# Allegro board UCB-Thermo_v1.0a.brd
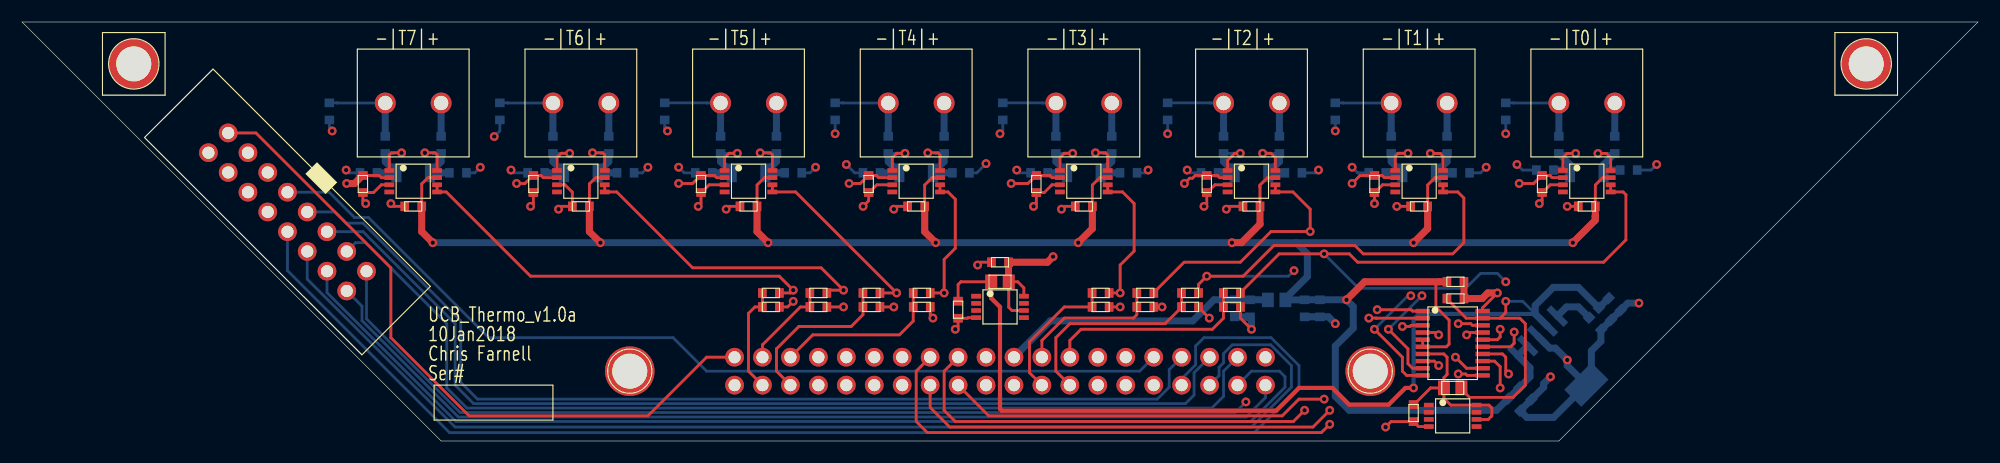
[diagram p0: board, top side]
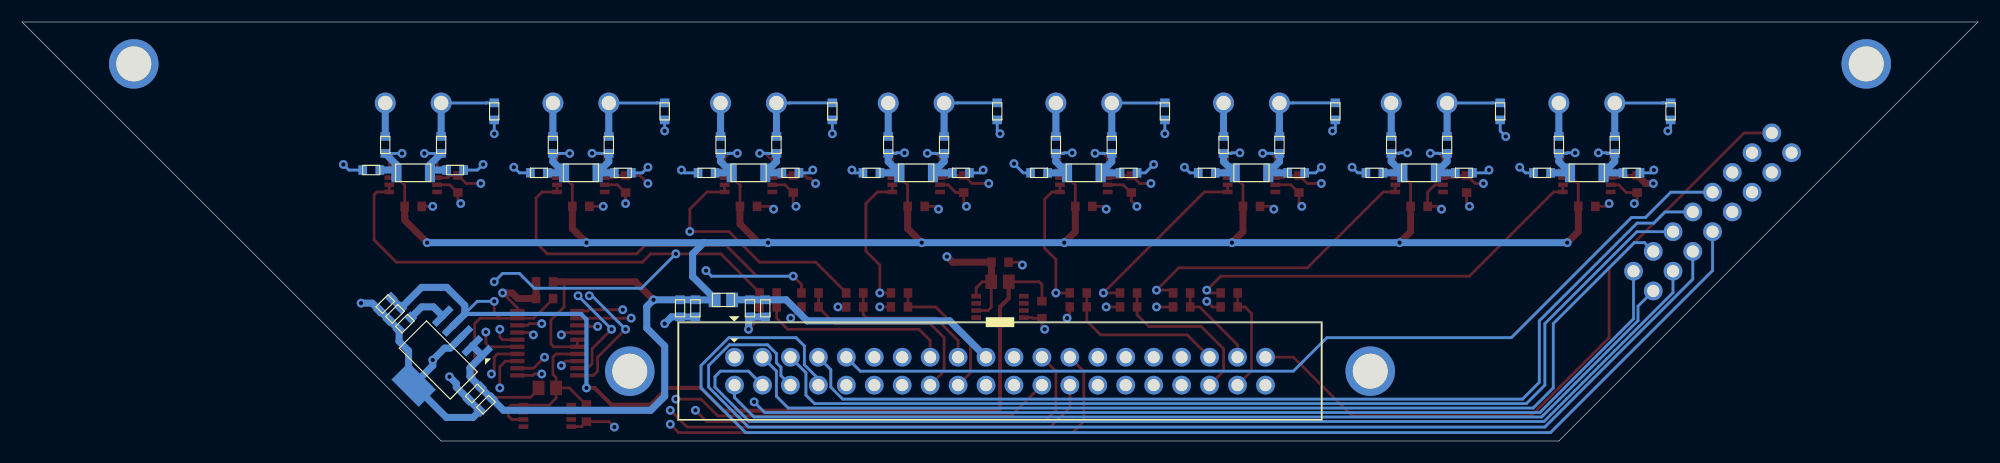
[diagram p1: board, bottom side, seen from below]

Outline 177.8 x 38.1 mm; copper layers: TOP, LAYER_2, LAYER_3, BOTTOM. Coordinates in mm from the lower left corner of the outline.
Outline path: 0,38.1 38.1,0 139.7,0 177.8,38.1 0,38.1

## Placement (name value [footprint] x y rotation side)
ADC1  AD7928BRUZ  [20-TSSOP]  130.05 8.89 0 top
C25  1uF  [C_0603]  110.24 12.06 270 bottom
C26  0.1uF  [C_0603]  111.63 12.06 270 bottom
C27  1uF  [C_0603]  116.59 12.06 270 bottom
C28  1uF  [C_0603]  85.09 11.94 270 top
C29  0.1uF  [C_0603]  117.98 12.06 270 bottom
C30  1uF  [C_0603]  88.9 16.26 0 top
C31  1uF  [C_0603]  135.64 3.3 315 bottom
C32  0.1uF  [C_0603]  136.65 4.32 315 bottom
C33  10nF  [C_0603]  143 10.67 315 bottom
C34  0.1uF  [C_0603]  143.89 11.56 315 bottom
C35  1uF  [C_0603]  144.78 12.45 315 bottom
C38  1uF  [C_0603]  130.3 14.48 0 top
C39  1uF  [C_0603]  130.3 12.95 0 top
C40  1uF  [C_0603]  126.49 2.54 90 top
C59  10uF  [C_1206]  142.24 24.38 180 bottom
C60  1uF  [C_0603]  146.05 24.64 180 bottom
C61  1uF  [C_0603]  138.43 24.64 180 bottom
C62  0.1uF  [C_0603]  142.24 21.34 180 top
C63  0.1uF  [C_0603]  138.18 23.37 90 top
C64  10uF  [C_1206]  127 24.38 180 bottom
C65  1uF  [C_0603]  130.81 24.38 180 bottom
C66  1uF  [C_0603]  123.19 24.38 180 bottom
C67  0.1uF  [C_0603]  127 21.34 180 top
C68  0.1uF  [C_0603]  122.94 23.37 90 top
C69  10uF  [C_1206]  111.76 24.38 180 bottom
C70  1uF  [C_0603]  115.57 24.38 180 bottom
C71  1uF  [C_0603]  107.95 24.38 180 bottom
C72  0.1uF  [C_0603]  111.76 21.34 180 top
C73  0.1uF  [C_0603]  107.7 23.37 90 top
C74  10uF  [C_1206]  96.52 24.38 180 bottom
C75  1uF  [C_0603]  100.58 24.38 180 bottom
C76  1uF  [C_0603]  92.46 24.38 180 bottom
C77  0.1uF  [C_0603]  96.52 21.34 180 top
C78  0.1uF  [C_0603]  92.2 23.37 90 top
C79  10uF  [C_1206]  81.28 24.38 180 bottom
C80  1uF  [C_0603]  85.34 24.38 180 bottom
C81  1uF  [C_0603]  77.22 24.38 180 bottom
C82  0.1uF  [C_0603]  81.28 21.34 180 top
C83  0.1uF  [C_0603]  76.96 23.37 90 top
C84  10uF  [C_1206]  66.04 24.38 180 bottom
C85  1uF  [C_0603]  70.1 24.38 180 bottom
C86  1uF  [C_0603]  61.98 24.38 180 bottom
C87  0.1uF  [C_0603]  66.04 21.34 180 top
C88  0.1uF  [C_0603]  61.72 23.37 90 top
C89  10uF  [C_1206]  50.8 24.38 180 bottom
C90  1uF  [C_0603]  54.86 24.38 180 bottom
C91  1uF  [C_0603]  46.74 24.38 180 bottom
C92  0.1uF  [C_0603]  50.8 21.34 180 top
C93  0.1uF  [C_0603]  46.48 23.37 90 top
C94  10uF  [C_1206]  35.56 24.38 180 bottom
C95  1uF  [C_0603]  39.62 24.38 180 bottom
C96  1uF  [C_0603]  31.5 24.38 180 bottom
C97  0.1uF  [C_0603]  35.56 21.34 180 top
C98  0.1uF  [C_0603]  30.99 23.37 90 top
J3  SFH11-PBPC-D20-ST-BK  [40-IDC-F_MNT]  88.9 6.35 270 bottom
J4  AWHW 16G-0202-T  [16-IDC-M]  24.13 20.83 225 top
J5  -  [1715721]  142.24 30.73 270 top
J6  -  [1715721]  127 30.73 270 top
J7  -  [1715721]  111.76 30.73 270 top
J8  -  [1715721]  96.52 30.73 270 top
J9  -  [1715721]  81.28 30.73 270 top
J10  -  [1715721]  66.04 30.73 270 top
J11  -  [1715721]  50.8 30.73 270 top
J12  -  [1715721]  35.56 30.73 270 top
L1  220  [L_0805]  114.05 12.83 0 bottom
MECH1  Mech_Hole  [4-40_SCREW]  10.16 34.29 0 top
MECH2  Mech_Hole  [4-40_SCREW]  167.64 34.29 0 top
R3  1k  [R_0805]  88.9 14.48 0 top
R8  1k  [R_0805]  130.05 4.83 180 top
R15  10k  [R_0603]  109.98 13.46 180 top
R16  15k  [R_0603]  109.98 12.19 0 top
R17  10k  [R_0603]  106.17 13.46 180 top
R18  15k  [R_0603]  106.17 12.19 0 top
R23  10k  [R_0603]  102.11 13.46 180 top
R24  15k  [R_0603]  102.11 12.19 0 top
R29  10k  [R_0603]  98.04 13.46 180 top
R30  15k  [R_0603]  98.04 12.19 0 top
R35  10k  [R_0603]  81.79 13.46 180 top
R36  15k  [R_0603]  81.79 12.19 0 top
R41  10k  [R_0603]  77.22 13.46 180 top
R42  15k  [R_0603]  77.22 12.19 0 top
R47  10k  [R_0603]  72.39 13.46 180 top
R48  15k  [R_0603]  72.39 12.19 0 top
R53  10k  [R_0603]  68.07 13.46 180 top
R54  15k  [R_0603]  68.07 12.19 0 top
R59  10k  [R_0603]  144.78 26.92 90 bottom
R60  10k  [R_0603]  139.7 26.92 90 bottom
R61  1Meg  [R_0603]  134.87 29.97 90 bottom
R62  1Meg  [R_0603]  119.38 29.97 90 bottom
R63  10k  [R_0603]  129.54 26.92 90 bottom
R64  10k  [R_0603]  124.46 26.92 90 bottom
R65  1Meg  [R_0603]  104.14 29.97 90 bottom
R66  10k  [R_0603]  114.3 26.92 90 bottom
R67  10k  [R_0603]  109.22 26.92 90 bottom
R68  1Meg  [R_0603]  89.15 29.97 90 bottom
R69  10k  [R_0603]  99.06 26.92 90 bottom
R70  10k  [R_0603]  93.98 26.92 90 bottom
R71  1Meg  [R_0603]  73.91 29.97 90 bottom
R72  10k  [R_0603]  83.82 26.92 90 bottom
R73  10k  [R_0603]  78.74 26.92 90 bottom
R74  1Meg  [R_0603]  58.42 29.97 90 bottom
R75  10k  [R_0603]  68.58 26.92 90 bottom
R76  10k  [R_0603]  63.5 26.92 90 bottom
R77  1Meg  [R_0603]  43.43 29.97 90 bottom
R78  10k  [R_0603]  53.34 26.92 90 bottom
R79  10k  [R_0603]  48.26 26.92 90 bottom
R80  1Meg  [R_0603]  27.94 29.97 90 bottom
R81  10k  [R_0603]  38.1 26.92 90 bottom
R82  10k  [R_0603]  33.02 26.92 90 bottom
U1  LT1009CZ  [8-MSOP]  88.9 12.19 0 top
U2  TPS79533  [SOT-223-6]  139.95 7.37 135 bottom
U4  LT1009CZ  [8-MSOP]  130.05 2.29 0 top
U7  AD8495ARMZ  [8-MSOP]  142.24 23.62 0 top
U8  AD8495ARMZ  [8-MSOP]  127 23.62 0 top
U9  AD8495ARMZ  [8-MSOP]  111.76 23.62 0 top
U10  AD8495ARMZ  [8-MSOP]  96.52 23.62 0 top
U11  AD8495ARMZ  [8-MSOP]  81.28 23.62 0 top
U12  AD8495ARMZ  [8-MSOP]  66.04 23.62 0 top
U13  AD8495ARMZ  [8-MSOP]  50.8 23.62 0 top
U14  AD8495ARMZ  [8-MSOP]  35.56 23.62 0 top

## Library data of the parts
ADC1 = AD7928BRUZ
C25-C35 C38-C40 C59-C98 = CAP NP
J3 = Header_2x20
J4 = Header_2x8
J5-J12 = Connector-2
L1 = Ind
MECH1 MECH2 = Mech_Hole
R3 R8 R15-R18 R23 R24 R29 R30 R35 R36 R41 R42 R47 R48 R53 R54 R59-R82 = R-Standard
U1 U4 = LT1009CZ
U2 = TPS795
U7-U14 = AD849X

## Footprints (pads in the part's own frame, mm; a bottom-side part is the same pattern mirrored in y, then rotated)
4-40_SCREW
  round 4.5 hole 3.175: 1(0,0)
8-MSOP
  rect 0.889x0.42 smd: 1(-2.17,0.975) 2(-2.17,0.325) 3(-2.17,-0.325) 4(-2.17,-0.975) 5(2.17,-0.975) 6(2.17,-0.325) 7(2.17,0.325) 8(2.17,0.975)
16-IDC-M
  round 1.7 hole 1.1: 1(-1.27,8.89) 2(1.27,8.89) 3(-1.27,6.35) 4(1.27,6.35) 5(-1.27,3.81) 6(1.27,3.81) 7(-1.27,1.27) 8(1.27,1.27) 9(-1.27,-1.27) 10(1.27,-1.27) 11(-1.27,-3.81) 12(1.27,-3.81) 13(-1.27,-6.35) 14(1.27,-6.35) 15(-1.27,-8.89) 16(1.27,-8.89)
20-TSSOP
  rect 1.3x0.4 smd: 1(-2.725,2.925) 2(-2.725,2.275) 3(-2.725,1.625) 4(-2.725,0.975) 5(-2.725,0.325) 6(-2.725,-0.325) 7(-2.725,-0.975) 8(-2.725,-1.625) 9(-2.725,-2.275) 10(-2.725,-2.925) 11(2.725,-2.925) 12(2.725,-2.275) 13(2.725,-1.625) 14(2.725,-0.975) 15(2.725,-0.325) 16(2.725,0.325) 17(2.725,0.975) 18(2.725,1.625) 19(2.725,2.275) 20(2.725,2.925)
40-IDC-F_MNT
  round 4.5 hole 3.175: (0,-33.655) (0,33.655)
  round 1.7 hole 1.1: 1(-1.27,-24.13) 2(1.27,-24.13) 3(-1.27,-21.59) 4(1.27,-21.59) 5(-1.27,-19.05) 6(1.27,-19.05) 7(-1.27,-16.51) 8(1.27,-16.51) 9(-1.27,-13.97) 10(1.27,-13.97) 11(-1.27,-11.43) 12(1.27,-11.43) 13(-1.27,-8.89) 14(1.27,-8.89) 15(-1.27,-6.35) 16(1.27,-6.35) 17(-1.27,-3.81) 18(1.27,-3.81) 19(-1.27,-1.27) 20(1.27,-1.27) 21(-1.27,1.27) 22(1.27,1.27) 23(-1.27,3.81) 24(1.27,3.81) 25(-1.27,6.35) 26(1.27,6.35) 27(-1.27,8.89) 28(1.27,8.89) 29(-1.27,11.43) 30(1.27,11.43) 31(-1.27,13.97) 32(1.27,13.97) 33(-1.27,16.51) 34(1.27,16.51) 35(-1.27,19.05) 36(1.27,19.05) 37(-1.27,21.59) 38(1.27,21.59) 39(-1.27,24.13) 40(1.27,24.13)
1715721
  round 1.9 hole 1.3: 1(0,2.54) 2(0,-2.54)
C_0603
  rect 0.787x0.864 smd: 1(-0.775,0) 2(0.775,0)
C_1206
  rect 0.914x1.702 smd: 1(-1.524,0) 2(1.524,0)
L_0805
  rect 1.08x1.321 smd: 1(-0.794,0) 2(0.794,0)
R_0603
  rect 0.787x0.864 smd: 1(-0.775,0) 2(0.775,0)
R_0805
  rect 1.08x1.321 smd: 1(-0.794,0) 2(0.794,0)
SOT-223-6
  rect 2.2x0.6 smd: 1(3.1,-2.54) 2(3.1,-1.27) 3(3.1,0) 4(3.1,1.27) 5(3.1,2.54)
  rect 2.2x3.5 smd: 6(-3.175,0)

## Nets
2V5_REF: C30.2 C63.2 C68.2 C73.2 C78.2 C83.2 C88.2 C93.2 C98.2 R3.2 U1.6(V+.) U1.8(V+) U7.2(REF) U8.2(REF) U9.2(REF) U10.2(REF) U11.2(REF) U12.2(REF) U13.2(REF) U14.2(REF)
3V3: ADC1.19(VDRIVE) C28.1 C34.1 C35.1 C39.1 R3.1 R8.1 U2.4(VOUT)
5V0: ADC1.5(AVDD) ADC1.6(AVDD.) C27.1 C29.1 C31.1 C32.1 C38.1 C62.1 C67.1 C72.1 C77.1 C82.1 C87.1 C92.1 C97.1 L1.2 U2.1(EN) U2.2(VIN) U7.7(+VS) U8.7(+VS) U9.7(+VS) U10.7(+VS) U11.7(+VS) U12.7(+VS) U13.7(+VS) U14.7(+VS)
5V_IDC: C25.1 C26.1 J3.19 J3.39 J4.15 L1.1
GND: ADC1.4(AGND) ADC1.8(AGND.) ADC1.17(AGND..) ADC1.20(AGND...) C25.2 C26.2 C27.2 C28.2 C29.2 C30.1 C31.2 C32.2 C33.2 C34.2 C35.2 C38.2 C39.2 C40.1 C60.1 C61.2 C62.2 C63.1 C65.1 C66.2 C67.2 C68.1 C70.1 C71.2 C72.2 C73.1 C75.1 C76.2 C77.2 C78.1 C80.1 C81.2 C82.2 C83.1 C85.1 C86.2 C87.2 C88.1 C90.1 C91.2 C92.2 C93.1 C95.1 C96.2 C97.2 C98.1 J3.20 J3.40 J4.16 R16.2 R18.2 R24.2 R30.2 R36.2 R42.2 R48.2 R54.2 R61.1 R62.1 R65.1 R68.1 R71.1 R74.1 R77.1 R80.1 U1.4(GND) U2.3(GND) U2.6(GND.) U4.4(GND) U7.3(-VS) U8.3(-VS) U9.3(-VS) U10.3(-VS) U11.3(-VS) U12.3(-VS) U13.3(-VS) U14.3(-VS)
IDC_ADC-0: J3.15 R15.2 R16.1
IDC_ADC-1: J3.16 R17.2 R18.1
IDC_ADC-2: J3.17 R23.2 R24.1
IDC_ADC-3: J3.18 R29.2 R30.1
IDC_ADC-4: J3.35 R35.2 R36.1
IDC_ADC-5: J3.36 R41.2 R42.1
IDC_ADC-6: J3.37 R47.2 R48.1
IDC_ADC-7: J3.38 R53.2 R54.1
IDC_IO-1: J3.1 J4.1
IDC_IO-2: J3.2 J4.2
IDC_IO-3: J3.3 J4.3
IDC_IO-4: J3.4 J4.4
IDC_IO-5: J3.5 J4.5
IDC_IO-6: J3.6 J4.6
IDC_IO-7: J3.7 J4.7
IDC_IO-8: J3.8 J4.8
IDC_IO-9: J3.9 J4.9
IDC_IO-10: J3.10 J4.10
IDC_IO-11: J3.11 J4.11
IDC_IO-12: J3.12 J4.12
IDC_IO-13: J3.13 J4.13
IDC_IO-14: J3.14 J4.14
SPI-ADC_5V-CH0: ADC1.16(VIN0) R15.1 U7.5(SENSE) U7.6(OUT)
SPI-ADC_5V-CH1: ADC1.15(VIN1) R17.1 U8.5(SENSE) U8.6(OUT)
SPI-ADC_5V-CH2: ADC1.14(VIN2) R23.1 U9.5(SENSE) U9.6(OUT)
SPI-ADC_5V-CH3: ADC1.13(VIN3) R29.1 U10.5(SENSE) U10.6(OUT)
SPI-ADC_5V-CH4: ADC1.12(VIN4) R35.1 U11.5(SENSE) U11.6(OUT)
SPI-ADC_5V-CH5: ADC1.11(VIN5) R41.1 U12.5(SENSE) U12.6(OUT)
SPI-ADC_5V-CH6: ADC1.10(VIN6) R47.1 U13.5(SENSE) U13.6(OUT)
SPI-ADC_5V-CH7: ADC1.9(VIN7) R53.1 U14.5(SENSE) U14.6(OUT)
SPI-ADC_CS: ADC1.3(CS) J3.24
SPI-ADC_DIN: ADC1.2(DIN) J3.25
SPI-ADC_DOUT: ADC1.18(DOUT) J3.26
SPI-ADC_SCLK: ADC1.1(SCLK) J3.23
N365232: ADC1.7(REF_IN) C40.2 R8.2 U4.6(V+.) U4.8(V+)
N370101: C33.1 U2.5(NR/FB)
N440352: C59.1 C60.2 R59.1 U7.8(+IN)
N440371: C59.2 C61.1 R60.1 U7.1(-IN)
N440428: J5.2(P2) R60.2 R61.2
N440435: J5.1(P1) R59.2
N443016: C64.1 C65.2 R63.1 U8.8(+IN)
N443028: C64.2 C66.1 R64.1 U8.1(-IN)
N443064: J6.2(P2) R62.2 R64.2
N443072: J6.1(P1) R63.2
N443968: C69.1 C70.2 R66.1 U9.8(+IN)
N443980: C69.2 C71.1 R67.1 U9.1(-IN)
N444016: J7.2(P2) R65.2 R67.2
N444024: J7.1(P1) R66.2
N444943: C74.1 C75.2 R69.1 U10.8(+IN)
N444955: C74.2 C76.1 R70.1 U10.1(-IN)
N444991: J8.2(P2) R68.2 R70.2
N444999: J8.1(P1) R69.2
N449385: C79.1 C80.2 R72.1 U11.8(+IN)
N449397: C79.2 C81.1 R73.1 U11.1(-IN)
N449433: J9.2(P2) R71.2 R73.2
N449441: J9.1(P1) R72.2
N449775: C84.1 C85.2 R75.1 U12.8(+IN)
N449787: C84.2 C86.1 R76.1 U12.1(-IN)
N449823: J10.2(P2) R74.2 R76.2
N449831: J10.1(P1) R75.2
N450165: C89.1 C90.2 R78.1 U13.8(+IN)
N450177: C89.2 C91.1 R79.1 U13.1(-IN)
N450213: J11.2(P2) R77.2 R79.2
N450221: J11.1(P1) R78.2
N452720: C94.1 C95.2 R81.1 U14.8(+IN)
N452732: C94.2 C96.1 R82.1 U14.1(-IN)
N452768: J12.2(P2) R80.2 R82.2
N452776: J12.1(P1) R81.2

Pads without a net: J3 21 22 27 28 29 30 31 32 33 34; MECH1 1; MECH2 1; U1 1 2 3 5 7; U4 1 2 3 5 7; U7 4; U8 4; U9 4; U10 4; U11 4; U12 4; U13 4; U14 4

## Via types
v1: diameter 0.8, hole 0.4, TOP to BOTTOM, 124 vias

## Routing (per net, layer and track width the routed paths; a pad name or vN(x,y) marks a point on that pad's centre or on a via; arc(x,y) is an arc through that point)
2V5_REF: length 165.7
  TOP w0.254: v1(75.18,23.42) 76.2,23.42 76.92,24.14 C83.2 77.67,24.14 77.87,23.95 U11.2 ; v1(89.92,23.42) 91.44,23.42 92.16,24.14 C78.2 93.43,24.14 93.63,23.95 U10.2 ; U14.2 32.67,23.95 32.47,24.14 C98.2 ; U1.6 89.99,11.87 89.69,12.16 R3.2 90.51,14.48 91.07,13.92 U1.8 ; v1(120.9,23.42) 121.62,24.13 121.92,24.13 121.93,24.14 C68.2 123.65,24.14 123.84,23.95 U8.2 ; v1(59.69,23.42) 60.96,23.42 61.68,24.14 C88.2 62.95,24.14 63.15,23.95 U12.2 ; v1(105.66,23.42) 106.14,23.9 106.4,23.9 106.65,24.14 C73.2 108.67,24.14 108.87,23.95 U9.2 ; v1(44.96,23.42) 45.72,23.42 46.44,24.14 C93.2 47.19,24.14 47.39,23.95 U13.2 ; v1(136.09,23.42) 137.41,23.42 138.14,24.14 C63.2 138.89,24.14 139.08,23.95 U7.2
  TOP w0.635: R3.2 89.67,14.5 C30.2 93.22,16.26 v1(93.73,16.76) ; C98.2 30.95,24.14 30.22,23.42 v1(29.51,23.42)
  LAYER_3 w0.635: 88.09,23.42 v1(89.92,23.42) v1(105.66,23.42) v1(120.9,23.42) v1(136.09,23.42) ; 88.09,23.42 88.9,22.61 88.9,17.4 90.15,16.15 93.11,16.15 v1(93.73,16.76) ; 88.09,23.42 v1(75.18,23.42) v1(59.69,23.42) v1(44.96,23.42) v1(29.51,23.42)
3V3: length 109.9
  TOP w0.254: 134.38,11.17 ADC1.19 131.28,11.17 129.53,12.92 C39.1 ; 134.38,11.17 134.38,11.19 134.87,11.68 v1(134.87,12.7) ; 134.38,11.17 136.15,11.17 136.65,10.67 136.65,5.08 135.54,3.97 131.58,3.97 130.84,4.71 R8.1 ; C28.1 85.09,14.22 85.34,14.48 R3.1
  TOP w0.381: v1(126.49,4.83) 125.75,4.83 124.22,3.3 120.65,3.3 119.13,4.83 116.08,4.83 114.01,2.76 89.07,2.76 88.9,2.92 88.9,12.19 88.11,12.99 R3.1
  BOTTOM w0.254: v1(134.87,12.7) 136.42,12.7 137.55,11.57
  BOTTOM w0.381: 137.55,11.55 127,11.55 126.49,11.05 v1(126.49,4.83)
  BOTTOM w0.635: U2.4 138.65,10.46 137.55,11.55 137.55,12.33 139.19,13.97 141.48,13.97 C34.1 C35.1
5V0: length 228.3
  TOP w0.254: U10.7 97.97,23.95 97.29,23.28 C77.1 ; U7.7 143.69,23.95 143.01,23.28 C62.1 ; C82.1 82.05,23.28 82.73,23.95 U11.7 ; U12.7 67.49,23.95 66.81,23.28 C87.1 ; 128.78,14.48 128.52,14.22 128.52,12.19 129.72,10.99 129.72,8.82 129.47,8.56 ADC1.6 ADC1.5 ; C67.1 127.77,23.28 128.45,23.95 U8.7 ; U13.7 52.14,23.95 51.57,23.38 C92.1 ; C97.1 36.33,23.38 36.9,23.95 U14.7 ; C72.1 112.53,23.1 112.52,23.11 112.52,23.26 113.21,23.95 U9.7
  TOP w0.635: C67.1 127.77,19.32 v1(126.49,18.03) ; v1(52.58,18.03) 51.57,19.04 C92.1 ; C38.1 122.03,14.48 v1(120.4,12.84) ; C77.1 97.29,19.32 v1(96.01,18.03) ; v1(109.98,18.03) 110.85,18.03 112.53,19.72 C72.1 ; v1(67.82,18.03) 66.81,19.04 C87.1 ; C62.1 143.01,20.43 143,20.42 143,20.07 v1(140.97,18.03) ; C97.1 36.33,19.04 v1(37.34,18.03) ; C82.1 82.05,19.04 v1(83.06,18.03)
  BOTTOM w0.635: v1(37.34,18.03) v1(52.58,18.03) v1(67.82,18.03) v1(83.06,18.03) v1(96.01,18.03) v1(109.98,18.03) 115.82,18.03 ; U2.2 U2.1 137.08,6.65 137.08,5.84 C32.1 C31.1 134.03,2.79 120.65,2.79 119.38,4.06 119.38,8.64 121.01,10.27 121.01,12.22 v1(120.4,12.84) C29.1 C27.1 116.57,12.83 L1.2 114.84,12.95 116.84,14.95 116.84,17.02 115.82,18.03 ; 115.82,18.03 v1(126.49,18.03) v1(140.97,18.03)
5V_IDC: length 122.3
  TOP w0.254: J4.15 21.26,28.01 33.53,15.75 33.53,9.4 40.64,2.29 56.9,2.29 62.23,7.62 J3.39
  LAYER_3 w0.254: J3.39 63.5,6.35 63.5,4.32 64.62,3.2 88.54,3.2 89.04,3.7 89.04,6.49 J3.19
  BOTTOM w0.635: L1.1 113.24,12.84 C26.1 C25.1 108.34,12.84 106.43,10.92 93.47,10.92 J3.19
GND: length 141.1
  TOP w0.254: R54.2 69.6,12.19 v1(70.1,12.7) ; v1(46.23,21.34) 46.48,21.59 C93.1 ; C82.2 79.5,21.34 v1(79.25,21.08) ; v1(64.01,21.08) 64.26,21.34 C87.2 ; U12.3 62.46,23.3 61.76,22.59 C88.1 61.72,21.59 v1(61.47,21.34) ; U7.3 138.92,23.3 138.21,22.59 C63.1 138.18,21.84 v1(137.92,21.59) ; R24.2 v1(103.63,12.19) ; U8.3 123.68,23.3 122.97,22.59 C68.1 v1(122.94,21.59) ; C77.2 94.74,21.34 v1(94.49,21.08) ; U11.3 77.7,23.3 77,22.59 C83.1 76.96,21.84 v1(76.45,21.34) ; R30.2 v1(99.82,12.19) ; R18.2 106.95,12.15 v1(107.92,11.18) ; v1(134.11,13.46) 132.77,12.12 ADC1.20 ; v1(91.95,21.34) 92.2,21.59 C78.1 92.92,22.59 93.63,23.3 U10.3 ; v1(107.44,21.34) 107.7,21.59 C73.1 107.73,22.59 108.44,23.3 U9.3 ; C72.2 109.73,21.34 v1(109.47,21.08) ; R36.2 82.56,11.42 v1(82.8,11.18) ; U1.4 86.01,11.22 85.95,11.16 C28.2 85.09,10.41 v1(84.84,10.16) ; v1(131.32,9.65) 131.53,9.87 ADC1.17 ; C30.1 87.12,16.26 v1(86.87,16) ; R42.2 v1(79.25,12.19) ; R16.2 110.76,11.16 v1(111.76,10.16) ; R48.2 v1(74.68,12.19) ; U13.3 49.35,23.3 50.03,22.63 C92.2 49.02,21.34 v1(48.77,21.08) ; v1(33.53,21.59) 33.78,21.34 C97.2 ; v1(31.24,21.59) 30.99,21.84 C98.1 31.96,22.59 32.67,23.3 U14.3 ; C67.2 v1(124.97,21.34) ; v1(123.95,1.27) 124.45,1.77 C40.1 126.95,1.31 U4.4 ; v1(128.78,6.86) 128.37,7.26 ADC1.8 ; v1(128.78,9.65) 128.56,9.87 ADC1.4 ; C62.2 v1(140.46,21.34)
  TOP w0.635: v1(134.11,13.46) 133.24,13.46 132.73,12.95 C39.2 C38.2
  BOTTOM w0.254: C86.2 60.2,24.38 v1(59.69,24.89) ; R68.1 89.15,28.19 v1(88.9,27.94) ; R71.1 v1(73.91,27.94) ; C65.1 132.59,24.38 v1(133.1,24.89) ; C95.1 41.15,24.38 v1(41.66,24.89) ; v1(74.93,25.15) 75.69,24.38 C81.2 ; C71.2 106.17,24.38 v1(105.92,24.64) ; C60.1 148.08,24.64 v1(148.59,25.15) ; v1(44.45,24.64) 44.7,24.38 C91.2 ; C61.2 136.4,24.64 v1(135.89,25.15) ; v1(42.93,27.69) 43.43,28.19 R77.1 ; C80.1 86.79,24.38 v1(87.63,25.22) ; C96.2 29.72,24.38 v1(29.46,24.64) ; C75.1 102.11,24.38 v1(102.36,24.64) ; v1(90.42,24.64) 90.68,24.38 C76.2 ; v1(120.9,24.89) 121.41,24.38 C66.2 ; C85.1 71.63,24.38 v1(72.14,24.89) ; R80.1 27.94,28.45 v1(28.19,28.19) ; R61.1 v1(134.87,27.94) ; R74.1 58.42,28.45 v1(58.67,28.19) ; C90.1 56.39,24.38 v1(56.9,24.89) ; v1(117.86,24.64) 117.6,24.38 C70.1 ; R65.1 v1(104.14,27.94) ; R62.1 v1(119.38,28.19)
  BOTTOM w0.635: v1(111.76,10.16) 111.76,11.16 C26.2 C25.2 ; U2.6 139.22,2.14 136.79,2.14 C31.2 C32.2 138.32,4.89 138.32,5.23 v1(138.94,5.84) ; U2.6 140.46,6.86 v1(140.46,7.37) 139.38,8.45 138.87,8.45 U2.3 ; U2.6 142.66,5.58 142.66,8.2 143.52,9.07 143.52,10.09 C33.2 C34.2 C35.2 145.97,12.54 v1(146.98,12.54) ; C27.2 C29.2 118.76,11.29 v1(119.38,10.67)
IDC_ADC-0: length 18.6
  TOP w0.254: R15.2 R16.1 109.21,11.16 108.2,10.16 96.27,10.16 95.25,9.14 J3.15
IDC_ADC-1: length 18.7
  TOP w0.254: R17.2 R18.1 105.4,12.15 103.91,10.67 95.25,10.67 93.98,9.4 93.98,6.35 J3.16
IDC_ADC-2: length 13.1
  TOP w0.254: J3.17 92.71,9.14 94.74,11.18 101.03,11.18 101.33,11.48 R24.1 R23.2
IDC_ADC-3: length 12.7
  TOP w0.254: R29.2 R30.1 94.74,12.19 91.58,9.03 91.58,6.21 J3.18
IDC_ADC-4: length 15.1
  TOP w0.254: R35.2 R36.1 81.01,10.91 79.76,9.65 71.88,9.65 J3.35
IDC_ADC-5: length 15
  TOP w0.254: J3.36 68.58,6.35 68.58,8.38 70.61,10.41 75.37,10.41 76.44,11.48 R42.1 R41.2
IDC_ADC-6: length 8.1
  TOP w0.254: J3.37 67.31,8.75 70.75,12.19 R48.1 R47.2
IDC_ADC-7: length 9.8
  TOP w0.254: R53.2 R54.1 66.62,12.19 66.04,11.61 66.04,6.35 J3.38
IDC_IO-1: length 93
  LAYER_3 w0.254: v1(111.25,3.56) 111.76,4.06 111.76,6.35 J3.1
  BOTTOM w0.254: v1(111.25,3.56) 110.29,2.59 39.83,2.59 31.31,11.1 J4.1
IDC_IO-2: length 90.9
  BOTTOM w0.254: J3.2 113.03,3.95 111.26,2.18 39.66,2.18 30.91,10.94 30.91,12.25 J4.2
IDC_IO-3: length 94.2
  BOTTOM w0.254: J3.3 109.22,6.35 109.22,4.06 108.15,3 40.44,3 38.61,4.83 38.61,10.67 31.24,18.03 30.32,18.03 J4.3
IDC_IO-4: length 101.2
  BOTTOM w0.254: J3.4 111.76,6.35 114.3,6.35 114.81,5.84 114.81,4.89 111.69,1.78 39.44,1.78 27.72,13.49 J4.4
IDC_IO-5: length 92.9
  BOTTOM w0.254: J3.5 106.54,6.21 106.54,4.18 105.77,3.4 41.05,3.4 39.37,5.08 39.37,10.67 31.01,19.03 J4.5
IDC_IO-6: length 111.7
  BOTTOM w0.254: J3.6 108.81,5.94 108.81,6.71 109.22,7.11 109.22,7.95 110.02,8.75 113.5,8.75 115.39,6.86 115.39,4.9 111.76,1.27 39.37,1.27 25.93,14.71 J4.6
IDC_IO-7: length 92.3
  BOTTOM w0.254: J3.7 104.28,6.49 104.28,4.89 103.2,3.81 41.4,3.81 39.88,5.33 39.88,10.92 30.99,19.81 29.46,19.81 28.45,20.83 J4.7
IDC_IO-8: length 120.2
  BOTTOM w0.254: J3.8 105.41,5.65 106.68,6.92 106.68,8.64 107.44,9.4 113.54,9.4 116.08,6.86 116.08,4.83 112.01,0.76 38.86,0.76 24.13,15.49 J4.8
IDC_IO-9: length 86
  BOTTOM w0.254: J4.9 27.92,22.62 30.23,20.32 31.5,20.32 42.42,9.4 59.18,9.4 62.23,6.35 101.6,6.35 J3.9
IDC_IO-10: length 90.3
  LAYER_3 w0.254: J3.10 100.08,2.29 39.28,2.29 22.33,19.23 J4.10
IDC_IO-11: length 96.4
  LAYER_3 w0.254: J4.11 23.57,25.65 25.65,25.65 37.59,13.72 37.59,5.59 40.39,2.79 98.3,2.79 99.2,3.7 99.2,5.55 100.33,6.68 J3.11
IDC_IO-12: length 101
  LAYER_3 w0.254: J4.12 20.54,20.36 39.12,1.78 102.11,1.78 104.14,3.81 104.14,5.84 103.63,6.35 101.6,6.35 J3.12
IDC_IO-13: length 127
  LAYER_3 w0.254: J3.13 97.79,9.14 98.3,9.65 108.46,9.65 109.22,8.89 109.22,4.06 105.92,0.76 38.86,0.76 17.02,22.61 17.02,24.38 18.85,26.22 J4.13
IDC_IO-14: length 116.8
  LAYER_3 w0.254: J4.14 18.74,21.46 38.93,1.27 103.63,1.27 106.68,4.32 106.68,8.64 106.17,9.14 99.82,9.14 99.2,8.52 99.2,6.49 J3.14
SPI-ADC_5V-CH0: length 70.4
  TOP w0.254: v1(134.37,10.16) 134.37,9.47 134.11,9.22 ADC1.16 ; R15.1 110.76,13.5 114.27,17.02 v1(118.36,17.02) 120.65,17.02 121.41,16.26 143.76,16.26 145.8,18.29 145.8,22.39 145.54,22.65 U7.5 U7.6
  LAYER_3 w0.254: v1(134.37,10.16) 135.89,11.68 135.89,12.78 134.87,13.8 v1(134.87,14.48)
  BOTTOM w0.254: v1(134.87,14.48) 134.11,15.24 132.59,15.24 131.24,13.89 121.49,13.89 v1(118.36,17.02)
SPI-ADC_5V-CH1: length 72
  TOP w0.254: U8.6 U8.5 130.52,22.65 131.06,22.1 131.06,18.03 130.05,17.02 121.92,17.02 121.16,17.78 113.79,17.78 111,14.99 v1(107.7,14.99) 106.95,14.24 R17.1 ; v1(135.64,9.91) 135.64,8.89 135.31,8.56 ADC1.15
  LAYER_3 w0.254: v1(115.63,15.49) 135.13,15.49 136.4,14.22 136.4,10.67 v1(135.64,9.91)
  BOTTOM w0.254: v1(115.63,15.49) 115.12,14.99 v1(107.7,14.99)
SPI-ADC_5V-CH2: length 69.8
  TOP w0.254: R23.1 102.88,13.5 105.64,16.26 110.74,16.26 113.54,19.05 v1(117.09,19.05) 117.09,21.08 115.53,22.65 U9.5 U9.6 ; ADC1.14 134.58,7.91 134.87,7.62 134.87,6.35 v1(135.13,6.1)
  LAYER_3 w0.254: v1(117.09,19.05) 119.89,19.05 121.92,17.02 136.14,17.02 139.45,13.72 139.45,8.13 134.37,3.05 133.6,3.05 133.1,3.56 133.1,5.33 133.86,6.1 v1(135.13,6.1)
SPI-ADC_5V-CH3: length 68.6
  TOP w0.254: ADC1.13 133.86,7.26 134.37,6.76 v1(134.37,4.83) ; R29.1 v1(99.82,13.46) 99.82,16 101.09,17.27 101.09,21.59 100.04,22.65 U10.5 U10.6
  LAYER_3 w0.254: v1(99.82,13.46) 99.82,14.22 101.85,16.26 135.38,16.26 138.18,13.46 138.18,7.96 135.05,4.83 v1(134.37,4.83)
SPI-ADC_5V-CH4: length 67.6
  TOP w0.254: ADC1.12 131.31,6.61 v1(130.3,7.62) ; U11.6 U11.5 84.17,22.65 84.84,21.98 84.84,17.53 83.82,16.51 v1(83.82,13.46) R35.1
  LAYER_3 w0.254: v1(130.3,7.62) 129.54,7.62 123.29,13.87 119.28,13.87 116.08,10.67 112.21,10.67 112.04,10.84 111.48,10.84 110.73,10.09 87.19,10.09 v1(83.82,13.46)
SPI-ADC_5V-CH5: length 80
  TOP w0.254: U12.6 U12.5 70.32,22.65 v1(79.5,13.46) R41.1 ; v1(130.56,6.1) 131.24,6.1 131.37,5.96 ADC1.11
  LAYER_3 w0.254: v1(79.5,13.46) 80.52,14.48 84.07,14.48 88.06,10.5 110.06,10.5 111.25,11.68 116.33,11.68 118.92,14.27 123.65,14.27 127.25,10.67 129.03,10.67 131.32,8.38 131.32,6.86 v1(130.56,6.1)
SPI-ADC_5V-CH6: length 95
  TOP w0.254: U13.6 U13.5 54.06,22.65 60.96,15.75 72.64,15.75 v1(74.68,13.72) 73.42,13.72 R47.1 ; ADC1.10 125.86,5.96 125.48,6.35 125.48,7.62 v1(122.94,10.16)
  LAYER_3 w0.254: v1(74.68,13.72) 75.95,14.99 84.33,14.99 88.39,10.92 106.17,10.92 107.44,12.19 116.08,12.19 118.57,14.68 124.76,14.68 v1(126.24,13.21)
  BOTTOM w0.254: v1(122.94,10.16) 125.98,13.21 v1(126.24,13.21)
SPI-ADC_5V-CH7: length 109.6
  TOP w0.254: v1(124.21,10.16) 125.98,8.38 125.98,7.02 126.39,6.61 ADC1.9 ; U14.6 U14.5 38.57,22.65 46.23,14.99 68.83,14.99 v1(70.1,13.72) 69.85,13.46 R53.1
  LAYER_3 w0.254: v1(70.1,13.72) 71.88,15.49 84.58,15.49 88.65,11.43 105.92,11.43 107.19,12.7 115.82,12.7 118.21,15.09 125.37,15.09 v1(127.25,13.21)
  BOTTOM w0.254: v1(127.25,13.21) v1(124.21,10.16)
SPI-ADC_CS: length 50.4
  TOP w0.254: ADC1.3 126.26,10.52 126.16,10.41 v1(125.48,10.41) ; v1(118.36,3.81) 116.08,3.81 114.55,2.29 87.88,2.29 J3.24
  LAYER_3 w0.254: v1(125.48,10.41) 125.48,4.57 124.46,3.56 119.89,3.56 119.63,3.81 v1(118.36,3.81)
SPI-ADC_DIN: length 64.7
  TOP w0.254: v1(122.43,11.18) 123.11,11.18 123.12,11.17 ADC1.2 ; J3.25 81.28,6.35 81.28,1.78 82.3,0.76 118.11,0.76 v1(118.87,1.52)
  LAYER_3 w0.254: v1(122.43,11.18) 121.49,11.18 121.32,11.35 118.28,11.35 117.35,10.41 117.35,3.05 v1(118.87,1.52)
SPI-ADC_DOUT: length 64.2
  TOP w0.254: J3.26 82.55,3.05 84.33,1.27 117.35,1.27 v1(118.87,2.79) ; ADC1.18 131.84,10.52 131.69,10.67 v1(130.56,10.67)
  LAYER_3 w0.254: v1(130.56,10.67) 132.08,10.67 132.33,10.41 132.33,4.06 132.08,3.81 125.73,3.81 124.71,2.79 v1(118.87,2.79)
SPI-ADC_SCLK: length 58
  TOP w0.254: ADC1.1 126.39,11.82 126.27,11.94 v1(123.19,11.94) ; v1(116.59,2.79) 115.57,1.78 84.84,1.78 83.82,2.79 83.82,6.35 J3.23
  LAYER_3 w0.254: v1(116.59,2.79) 116.59,10.41 118.11,11.94 v1(123.19,11.94)
N365232: length 16.5
  TOP w0.254: ADC1.7 129.25,7.91 129.54,7.62 129.54,6.05 129.25,5.77 R8.2 ; R8.2 129.25,3.89 129.88,3.26 U4.8 133.35,3.26 133.6,3.01 133.6,2.29 133.28,1.96 U4.6 ; R8.2 128.04,4.83 126.53,3.31 C40.2
N370101: length 3.6
  BOTTOM w0.635: U2.5 140.4,12.19 141.48,12.19 C33.1
N440352: length 7.8
  TOP w0.254: U7.8 144.41,25.77 144.03,26.15 v1(143.26,26.15)
  BOTTOM w0.254: v1(143.26,26.15) R59.1
  BOTTOM w0.635: C60.2 144.02,24.64 C59.1 143.76,25.13 R59.1
N440371: length 7.8
  TOP w0.254: v1(141.22,26.15) 140.45,26.15 140.07,25.77 U7.1
  BOTTOM w0.254: v1(141.22,26.15) R60.1
  BOTTOM w0.635: R60.1 140.72,25.13 C59.2 140.46,24.64 C61.1
N440428: length 7.9
  BOTTOM w0.254: J5.2 135.6,30.73 135.59,30.75 R61.2
  BOTTOM w0.635: R60.2 J5.2
N440435: length 3
  BOTTOM w0.635: R59.2 J5.1
N443016: length 7.8
  TOP w0.254: v1(128.02,26.15) 128.92,26.15 129.17,25.9 U8.8
  BOTTOM w0.254: v1(128.02,26.15) R63.1
  BOTTOM w0.635: C65.2 C64.1 129.54,25.4 R63.1
N443028: length 7.8
  TOP w0.254: U8.1 124.83,25.91 125.08,26.16 v1(125.98,26.16)
  BOTTOM w0.254: R64.1 125.17,26.15 125.18,26.16 v1(125.98,26.16)
  BOTTOM w0.635: C66.1 C64.2 124.46,25.4 R64.1
N443064: length 8.1
  BOTTOM w0.254: J6.2 120.1,30.73 120.09,30.75 R62.2
  BOTTOM w0.635: J6.2 R64.2
N443072: length 3
  BOTTOM w0.635: J6.1 R63.2
N443968: length 7.7
  TOP w0.254: v1(112.78,26.16) 113.54,26.16 113.93,25.77 U9.8
  BOTTOM w0.254: R66.1 113.47,26.15 113.46,26.16 v1(112.78,26.16)
  BOTTOM w0.635: C70.2 C69.1 114.3,25.4 R66.1
N443980: length 7.6
  TOP w0.254: v1(110.74,26.16) 110.24,26.16 109.59,25.52 U9.1
  BOTTOM w0.254: v1(110.74,26.16) 109.94,26.16 109.93,26.15 R67.1
  BOTTOM w0.635: C71.1 C69.2 109.22,25.4 R67.1
N444016: length 8.1
  BOTTOM w0.254: R65.2 107.98,30.75 107.99,30.73 J7.2
  BOTTOM w0.635: R67.2 J7.2
N444024: length 3
  BOTTOM w0.635: R66.2 J7.1
N444943: length 8.1
  TOP w0.254: U10.8 98.69,26.02 98.51,26.2 v1(97.58,26.2)
  BOTTOM w0.254: v1(97.58,26.2) 98.29,26.2 98.35,26.15 R69.1
  BOTTOM w0.635: R69.1 99.06,25.4 C74.1 C75.2
N444955: length 8
  TOP w0.254: U10.1 94.35,25.77 94.74,26.16 v1(95.5,26.16)
  BOTTOM w0.254: v1(95.5,26.16) 94.7,26.16 94.69,26.15 R70.1
  BOTTOM w0.635: R70.1 93.98,25.4 C74.2 C76.1
N444991: length 7.9
  BOTTOM w0.254: R68.2 92.74,30.75 92.75,30.73 J8.2
  BOTTOM w0.635: R70.2 J8.2
N444999: length 3
  BOTTOM w0.635: R69.2 J8.1
N449385: length 8.1
  TOP w0.254: v1(82.34,26.2) 83.27,26.2 83.45,26.02 U11.8
  BOTTOM w0.254: v1(82.34,26.2) 83.05,26.2 83.11,26.15 R72.1
  BOTTOM w0.635: R72.1 83.82,25.4 C79.1 C80.2
N449397: length 8
  TOP w0.254: U11.1 79.11,25.77 79.5,26.16 v1(80.26,26.16)
  BOTTOM w0.254: v1(80.26,26.16) 79.46,26.16 79.45,26.15 R73.1
  BOTTOM w0.635: R73.1 78.74,25.4 C79.2 C81.1
N449433: length 7.9
  BOTTOM w0.254: R71.2 74.63,30.75 74.64,30.73 J9.2
  BOTTOM w0.635: R73.2 J9.2
N449441: length 3
  BOTTOM w0.635: R72.2 J9.1
N449775: length 8.1
  TOP w0.254: v1(67.1,26.2) 68.03,26.2 68.21,26.02 U12.8
  BOTTOM w0.254: R75.1 67.87,26.15 67.81,26.2 v1(67.1,26.2)
  BOTTOM w0.635: R75.1 68.58,25.4 C84.1 C85.2
N449787: length 8
  TOP w0.254: v1(65.02,26.16) 64.26,26.16 63.87,25.77 U12.1
  BOTTOM w0.254: R76.1 64.21,26.15 64.22,26.16 v1(65.02,26.16)
  BOTTOM w0.635: R76.1 63.5,25.4 C84.2 C86.1
N449823: length 8.1
  BOTTOM w0.254: R74.2 62.26,30.75 62.27,30.73 J10.2
  BOTTOM w0.635: J10.2 R76.2
N449831: length 3
  BOTTOM w0.635: J10.1 R75.2
N450165: length 8.1
  TOP w0.254: U13.8 52.97,26.02 52.79,26.2 v1(51.86,26.2)
  BOTTOM w0.254: R78.1 52.63,26.15 52.57,26.2 v1(51.86,26.2)
  BOTTOM w0.635: R78.1 53.34,25.4 C89.1 C90.2
N450177: length 8
  TOP w0.254: U13.1 48.63,25.77 49.02,26.16 v1(49.78,26.16)
  BOTTOM w0.254: R79.1 48.97,26.15 48.98,26.16 v1(49.78,26.16)
  BOTTOM w0.635: R79.1 48.26,25.4 C89.2 C91.1
N450213: length 7.9
  BOTTOM w0.254: R77.2 44.15,30.75 44.16,30.73 J11.2
  BOTTOM w0.635: R79.2 J11.2
N450221: length 3
  BOTTOM w0.635: R78.2 J11.1
N452720: length 8.1
  TOP w0.254: v1(36.62,26.2) 37.55,26.2 37.73,26.02 U14.8
  BOTTOM w0.254: R81.1 37.39,26.15 37.33,26.2 v1(36.62,26.2)
  BOTTOM w0.635: C95.2 C94.1 38.1,25.4 R81.1
N452732: length 8.1
  TOP w0.254: U14.1 33.39,26.02 33.57,26.2 v1(34.5,26.2)
  BOTTOM w0.254: v1(34.5,26.2) 33.79,26.2 33.73,26.15 R82.1
  BOTTOM w0.635: R82.1 33.02,25.4 C94.2 C96.1
N452768: length 8.1
  BOTTOM w0.254: R80.2 28.65,30.75 28.66,30.73 J12.2
  BOTTOM w0.635: R82.2 J12.2
N452776: length 3
  BOTTOM w0.635: R81.2 J12.1

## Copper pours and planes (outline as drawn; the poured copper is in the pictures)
GND on LAYER_2: 38.1,0.76 139.7,0.76 164.59,25.65 164.59,37.34 13.21,37.34 13.21,25.65

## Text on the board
Ref Des/Silkscreen Top: -|T7|+ | UCB_Thermo_v1.0a | 10Jan2018 | Chris Farnell | Ser# | -|T6|+ | -|T5|+ | -|T4|+ | -|T3|+ | -|T2|+ | -|T1|+ | -|T0|+
